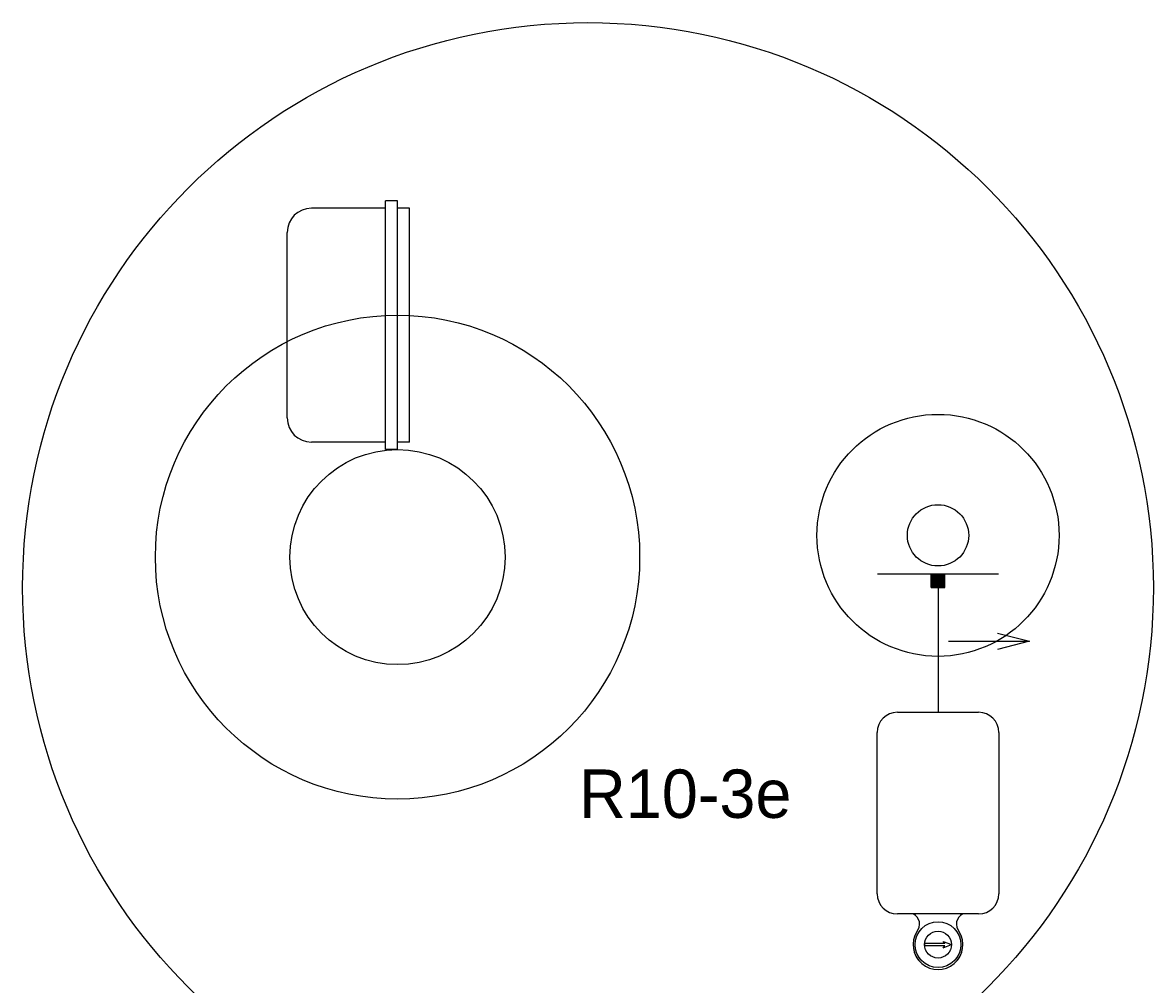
# Model space of a CAD drawing. Extents: x 1370050 to 1370716, y 380076 to 380502.
# Drawn here: x 1370462.4 to 1370532.5, y 380202.5 to 380262.1 of the extents above; entities that cross this region are included whole.
import ezdxf

# ---------------------------------------------------------------- set-up
doc = ezdxf.new("R2010")
doc.units = 0
doc.layers.add('T_Drafting', color=7, linetype='Continuous')

msp = doc.modelspace()

# ---------------------------------------------------------------- linework, layer by layer
at = {"layer": 'T_Drafting'}
for p, q in [((1370484.881, 380235.651), (1370484.881, 380251.068)), ((1370485.631, 380251.068), (1370484.881, 380251.068)), ((1370485.631, 380235.651), (1370485.631, 380251.068)), ((1370484.881, 380250.609), (1370480.297, 380250.609)), ((1370486.381, 380250.609), (1370485.631, 380250.609)), ((1370486.381, 380236.109), (1370486.381, 380250.609)), ((1370478.797, 380237.609), (1370478.797, 380249.109)), ((1370484.881, 380236.109), (1370480.297, 380236.109)), ((1370486.381, 380236.109), (1370485.631, 380236.109)), ((1370485.631, 380235.651), (1370484.881, 380235.651)), ((1370522.864, 380227.931), (1370515.364, 380227.931)), ((1370518.697, 380227.098), (1370518.697, 380227.931)), ((1370518.697, 380227.104), (1370519.524, 380227.931)), ((1370518.697, 380227.118), (1370519.51, 380227.931)), ((1370518.697, 380227.132), (1370519.496, 380227.931)), ((1370518.697, 380227.146), (1370519.482, 380227.931)), ((1370518.697, 380227.16), (1370519.468, 380227.931)), ((1370518.697, 380227.174), (1370519.454, 380227.931)), ((1370518.697, 380227.189), (1370519.44, 380227.931)), ((1370518.697, 380227.203), (1370519.425, 380227.931)), ((1370518.697, 380227.217), (1370519.411, 380227.931)), ((1370518.697, 380227.231), (1370519.397, 380227.931)), ((1370518.697, 380227.245), (1370519.383, 380227.931)), ((1370518.697, 380227.259), (1370519.369, 380227.931)), ((1370518.697, 380227.273), (1370519.355, 380227.931)), ((1370518.697, 380227.288), (1370519.341, 380227.931)), ((1370518.697, 380227.302), (1370519.326, 380227.931)), ((1370518.697, 380227.316), (1370519.312, 380227.931)), ((1370518.697, 380227.33), (1370519.298, 380227.931)), ((1370518.697, 380227.344), (1370519.284, 380227.931)), ((1370518.697, 380227.358), (1370519.27, 380227.931)), ((1370518.697, 380227.372), (1370519.256, 380227.931)), ((1370518.697, 380227.387), (1370519.242, 380227.931)), ((1370518.697, 380227.401), (1370519.227, 380227.931)), ((1370518.697, 380227.415), (1370519.213, 380227.931)), ((1370518.697, 380227.429), (1370519.199, 380227.931)), ((1370518.697, 380227.443), (1370519.185, 380227.931)), ((1370518.697, 380227.457), (1370519.171, 380227.931)), ((1370518.697, 380227.471), (1370519.157, 380227.931)), ((1370518.697, 380227.486), (1370519.143, 380227.931)), ((1370518.697, 380227.5), (1370519.128, 380227.931)), ((1370518.697, 380227.514), (1370519.114, 380227.931)), ((1370518.697, 380227.528), (1370519.1, 380227.931)), ((1370518.697, 380227.542), (1370519.086, 380227.931)), ((1370518.697, 380227.556), (1370519.072, 380227.931)), ((1370518.697, 380227.57), (1370519.058, 380227.931)), ((1370518.697, 380227.585), (1370519.044, 380227.931)), ((1370518.697, 380227.599), (1370519.029, 380227.931)), ((1370518.697, 380227.613), (1370519.015, 380227.931)), ((1370518.697, 380227.627), (1370519.001, 380227.931)), ((1370518.697, 380227.641), (1370518.987, 380227.931)), ((1370518.697, 380227.655), (1370518.973, 380227.931)), ((1370518.697, 380227.669), (1370518.959, 380227.931)), ((1370518.697, 380227.684), (1370518.945, 380227.931)), ((1370518.697, 380227.698), (1370518.93, 380227.931)), ((1370518.697, 380227.712), (1370518.916, 380227.931)), ((1370518.697, 380227.726), (1370518.902, 380227.931)), ((1370518.697, 380227.74), (1370518.888, 380227.931)), ((1370518.697, 380227.754), (1370518.874, 380227.931)), ((1370518.697, 380227.768), (1370518.86, 380227.931)), ((1370518.697, 380227.783), (1370518.846, 380227.931)), ((1370518.697, 380227.797), (1370518.831, 380227.931)), ((1370518.697, 380227.811), (1370518.817, 380227.931)), ((1370518.697, 380227.825), (1370518.803, 380227.931)), ((1370518.697, 380227.839), (1370518.789, 380227.931)), ((1370518.697, 380227.853), (1370518.775, 380227.931)), ((1370518.697, 380227.867), (1370518.761, 380227.931)), ((1370518.697, 380227.882), (1370518.747, 380227.931)), ((1370518.697, 380227.896), (1370518.732, 380227.931)), ((1370518.697, 380227.91), (1370518.718, 380227.931)), ((1370518.697, 380227.924), (1370518.704, 380227.931)), ((1370518.705, 380227.098), (1370519.53, 380227.923)), ((1370518.719, 380227.098), (1370519.53, 380227.909)), ((1370518.733, 380227.098), (1370519.53, 380227.895)), ((1370518.748, 380227.098), (1370519.53, 380227.881)), ((1370518.762, 380227.098), (1370519.53, 380227.866)), ((1370518.776, 380227.098), (1370519.53, 380227.852)), ((1370518.79, 380227.098), (1370519.53, 380227.838)), ((1370518.804, 380227.098), (1370519.53, 380227.824)), ((1370518.818, 380227.098), (1370519.53, 380227.81)), ((1370518.832, 380227.098), (1370519.53, 380227.796)), ((1370518.847, 380227.098), (1370519.53, 380227.782)), ((1370518.861, 380227.098), (1370519.53, 380227.767)), ((1370518.875, 380227.098), (1370519.53, 380227.753)), ((1370518.889, 380227.098), (1370519.53, 380227.739)), ((1370518.903, 380227.098), (1370519.53, 380227.725)), ((1370518.917, 380227.098), (1370519.53, 380227.711)), ((1370518.931, 380227.098), (1370519.53, 380227.697)), ((1370518.946, 380227.098), (1370519.53, 380227.683)), ((1370518.96, 380227.098), (1370519.53, 380227.668)), ((1370518.974, 380227.098), (1370519.53, 380227.654)), ((1370518.988, 380227.098), (1370519.53, 380227.64)), ((1370519.002, 380227.098), (1370519.53, 380227.626)), ((1370519.016, 380227.098), (1370519.53, 380227.612)), ((1370519.03, 380227.098), (1370519.53, 380227.598)), ((1370519.045, 380227.098), (1370519.53, 380227.584)), ((1370519.059, 380227.098), (1370519.53, 380227.569)), ((1370519.073, 380227.098), (1370519.53, 380227.555)), ((1370519.087, 380227.098), (1370519.53, 380227.541)), ((1370519.101, 380227.098), (1370519.53, 380227.527)), ((1370519.53, 380227.098), (1370519.53, 380227.931)), ((1370518.697, 380227.098), (1370519.53, 380227.098)), ((1370519.114, 380227.098), (1370519.114, 380219.362)), ((1370519.115, 380227.098), (1370519.53, 380227.513)), ((1370519.129, 380227.098), (1370519.53, 380227.499)), ((1370519.144, 380227.098), (1370519.53, 380227.485)), ((1370519.158, 380227.098), (1370519.53, 380227.47)), ((1370519.172, 380227.098), (1370519.53, 380227.456)), ((1370519.186, 380227.098), (1370519.53, 380227.442)), ((1370519.2, 380227.098), (1370519.53, 380227.428)), ((1370519.214, 380227.098), (1370519.53, 380227.414)), ((1370519.228, 380227.098), (1370519.53, 380227.4)), ((1370519.243, 380227.098), (1370519.53, 380227.386)), ((1370519.257, 380227.098), (1370519.53, 380227.371)), ((1370519.271, 380227.098), (1370519.53, 380227.357)), ((1370519.285, 380227.098), (1370519.53, 380227.343)), ((1370519.299, 380227.098), (1370519.53, 380227.329)), ((1370519.313, 380227.098), (1370519.53, 380227.315)), ((1370519.327, 380227.098), (1370519.53, 380227.301)), ((1370519.342, 380227.098), (1370519.53, 380227.287)), ((1370519.356, 380227.098), (1370519.53, 380227.272)), ((1370519.37, 380227.098), (1370519.53, 380227.258)), ((1370519.384, 380227.098), (1370519.53, 380227.244)), ((1370519.398, 380227.098), (1370519.53, 380227.23)), ((1370519.412, 380227.098), (1370519.53, 380227.216)), ((1370519.426, 380227.098), (1370519.53, 380227.202)), ((1370519.441, 380227.098), (1370519.53, 380227.188)), ((1370519.455, 380227.098), (1370519.53, 380227.173)), ((1370519.469, 380227.098), (1370519.53, 380227.159)), ((1370519.483, 380227.098), (1370519.53, 380227.145)), ((1370519.497, 380227.098), (1370519.53, 380227.131)), ((1370519.511, 380227.098), (1370519.53, 380227.117)), ((1370519.525, 380227.098), (1370519.53, 380227.103)), ((1370519.758, 380223.764), (1370524.791, 380223.764)), ((1370516.597, 380219.362), (1370521.63, 380219.362)), ((1370515.347, 380208.112), (1370515.347, 380218.112)), ((1370522.88, 380218.112), (1370522.88, 380208.112)), ((1370521.63, 380206.862), (1370516.597, 380206.862)), ((1370519.441, 380205.162), (1370519.947, 380204.962)), ((1370519.541, 380205.037), (1370519.441, 380205.162)), ((1370518.286, 380205.037), (1370518.286, 380204.887)), ((1370519.541, 380205.037), (1370518.286, 380205.037)), ((1370519.541, 380204.887), (1370518.286, 380204.887)), ((1370519.441, 380204.762), (1370519.947, 380204.962)), ((1370519.441, 380204.762), (1370519.541, 380204.887))]:
    msp.add_line(p, q, dxfattribs=at)
msp.add_lwpolyline([(1370522.791, 380224.264), (1370524.791, 380223.764), (1370522.791, 380223.264)], dxfattribs=at)
for centre, radius in [((1370497.43, 380227.088), 35.026), ((1370485.631, 380228.984), 15), ((1370519.114, 380230.331), 7.5), ((1370485.631, 380228.984), 6.667), ((1370519.114, 380230.331), 1.9), ((1370519.114, 380204.962), 1.417), ((1370519.114, 380204.962), 0.833)]:
    msp.add_circle(centre, radius, dxfattribs=at)
for centre, radius, start, end in [((1370480.297, 380249.109), 1.5, 90, 180), ((1370480.297, 380237.609), 1.5, 180, 270), ((1370516.597, 380218.112), 1.25, 90, 180), ((1370521.63, 380218.112), 1.25, 0, 90), ((1370516.597, 380208.112), 1.25, 180, 270), ((1370521.63, 380208.112), 1.25, 270, 0), ((1370517.274, 380206.228), 0.7, 318.19721, 64.80442), ((1370520.953, 380206.228), 0.7, 115.19558, 221.80279), ((1370519.114, 380204.962), 1.542, 148.74024, 227.49336), ((1370519.114, 380204.962), 1.542, 148.74024, 31.25976), ((1370519.114, 380204.962), 1.542, 312.50664, 31.25976)]:
    msp.add_arc(centre, radius, start, end, dxfattribs=at)

# ---------------------------------------------------------------- texts
msp.add_text('R10-3e', height=3, dxfattribs=at).set_placement((1370496.876, 380212.817))

doc.saveas('drawing.dxf')
